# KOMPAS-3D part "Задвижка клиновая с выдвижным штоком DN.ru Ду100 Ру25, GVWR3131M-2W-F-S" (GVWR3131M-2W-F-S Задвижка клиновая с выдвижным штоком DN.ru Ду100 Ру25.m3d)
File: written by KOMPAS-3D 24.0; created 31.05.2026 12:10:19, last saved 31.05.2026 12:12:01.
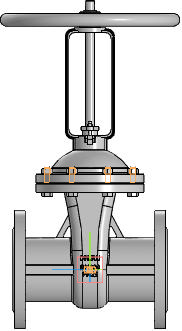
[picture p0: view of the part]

Document properties: Автор: R2D2; Полное имя файла: E:\Работа\Зайцев\GVWR3131M-2W-F-S Задвижка клиновая 30нж64нж DN.ru  Ду50-150 Ру25\исходные данные\DN100\dn100\GVWR3131M-2W-F-S Задвижка клиновая с выдвижным штоком DN.ru Ду100 Ру25.m3d

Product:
- Component [detail]: Деталь2  | qty 1  | pos. 1  | Автор: R2D2; additional columns: Типовые; source file: ..\Деталь2 Деталь2.m3d
- Component [detail]: ANSI B18.2.4.2M - M5x0,8 - 8  | designation ANSI B18.2.4.2M - M5x0,8  | qty 2  | pos. 2  | Комментарий: Типы метрических   шестигранных гаек   2; Автор: R2D2; additional columns: Сталь, мягкая; source file: ..\ANSI B18.2.4.2M - M5x0,8 ANSI B18.2.4.2M - M5x0,8 - 8.m3d
- Component [detail]: Деталь1  | qty 1  | pos. 3  | additional columns: Типовые; source file: ..\2.m3d
- Component [detail]: Деталь1  | qty 1  | pos. 3  | Автор: R2D2; additional columns: Типовые; source file: ..\3.m3d
- Component [detail]: Деталь1  | qty 2  | pos. 3  | Автор: R2D2; additional columns: Типовые; source file: ..\1.m3d
- Component [standard]: Болт М12-6gx50.88.45Г.019 ГОСТ 7798-70  | qty 8  | Материал: Сталь 45Г (density 7850 kg/m3); Масса: 0.06053; Раздел спецификации: Стандартные изделия; Рассекать на разрезах: no; additional columns: BOSimple***Material:39848d99-529e-4aa2-825c-393daa009d15
- Component [standard]: Гайка М12-6H ГОСТ 5915-70  | qty 24  | Масса: 0.0184; Раздел спецификации: Стандартные изделия; Рассекать на разрезах: no
- Part/product: Задвижка клиновая с выдвижным штоком DN.ru Ду100 Ру25  | designation GVWR3131M-2W-F-S
    Масса: 29
    Раздел спецификации: Прочие изделия
    Примечание: D040-07876

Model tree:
1. Массив по концентрической сетке:1  (labels: Грань.Твердое тело1)  (8 pattern instances)
     Шаг 2 = 360
2. Массив по концентрической сетке:2  (labels: Грань.Твердое тело1)  (2 pattern instances)
     Шаг 2 = 360
3. Элемент выдавливания:1  (with: Грань.Элемент выдавливания:2, Грань.Элемент выдавливания:1)
     Расстояние 1 = 88.75
4. Элемент выдавливания:2  (with: Грань.Элемент выдавливания:1, Грань.Элемент вращения:1)
     Расстояние 1 = 46.5338
5. Элемент выдавливания:3  (with: Грань.Элемент выдавливания:1, Грань.Элемент вращения:1)
     Расстояние 1 = 40.7931
6. Эскиз:1
7. Элемент выдавливания:4  (with: Грань.Элемент выдавливания:1, Грань.Элемент вращения:1)  (labels: Грань.Твердое тело1; Грань.Solid1; Твердое тело1)
     Расстояние 1 = 76; Смещение 1 = 1; Расстояние = -525; Расстояние = -150; Ориентация = 2

Referenced files in E:\Работа\Зайцев\GVWR3131M-2W-F-S Задвижка клиновая 30нж64нж DN.ru  Ду50-150 Ру25\исходные данные\DN100\: Деталь2 Деталь2.m3d, ANSI B18.2.4.2M - M5x0,8 ANSI B18.2.4.2M - M5x0,8 - 8.m3d, 2.m3d, 3.m3d, 1.m3d
Referenced files in C:\Program Files\ASCON\KOMPAS-3D v24\Libs\PolynomLib\DATA\vault\Methods\Kompas\3D\: PLib_Bolt_1_900.m3d, PLib_Nut_OST92_900.m3d
Referenced files in E:\Работа\Зайцев\GVWR3131M-2W-F-S Задвижка клиновая с выдвижным штоком DN.ru Ду50-200 Ру63\DN100\исходные материалы\: 1.m3d, ANSI B18.2.4.2M - M5x0,8 ANSI B18.2.4.2M - M5x0,8 - 8.m3d
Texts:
  BOSimple***PART:25ccc031-f2ed-a43b-e633-090566d53ffa***SHORTLOC:Root±30±20±10±80±10±©{}30±©{BASE}130±290[9;Цинковое, хроматированное;Сталь 45Г ГОСТ 4543-2016;50;12;19;1,75;8.8]
  BOSimple***Material:39848d99-529e-4aa2-825c-393daa009d15
  BOSimple***PART:dfaf85ed-3e43-003f-b29c-9c5b054070d3***SHORTLOC:Root±30±10±20±©{}110±10±50±60[Нет;Без покрытия;Без указания материала;-;12;1,75;19]
  GVWR3131M-2W-F-S
  DN100
  GOST 26.020 Pr3
  PN25
  Деталь2 Деталь2
  ANSI B18.2.4.2M - M5x0,8 ANSI B18.2.4.2M - M5x0,8 - 8 (1)
  Деталь1 Деталь1
  Деталь1 Деталь1 (1)
  Деталь1 Деталь1 (2)
  Болт М12-6gx50.88.45Г.019 ГОСТ 7798-70 (1)
  hole1
  hole2
  Гайка М12-6H ГОСТ 5915-70 (1)
  bcut1
  hcut1
  cut1
  Гайка М12-6H ГОСТ 5915-70 (2)
  Гайка М12-6H ГОСТ 5915-70 (3)
  Гайка М12-6H ГОСТ 5915-70 (4)
  Гайка М12-6H ГОСТ 5915-70 (5)
  Гайка М12-6H ГОСТ 5915-70 (6)
  Болт М12-6gx50.88.45Г.019 ГОСТ 7798-70 (2)
  Гайка М12-6H ГОСТ 5915-70 (7)
  Гайка М12-6H ГОСТ 5915-70 (8)
  Гайка М12-6H ГОСТ 5915-70 (9)
  Болт М12-6gx50.88.45Г.019 ГОСТ 7798-70 (3)
  Гайка М12-6H ГОСТ 5915-70 (10)
  Гайка М12-6H ГОСТ 5915-70 (11)
  Гайка М12-6H ГОСТ 5915-70 (12)
  Болт М12-6gx50.88.45Г.019 ГОСТ 7798-70 (4)
  Гайка М12-6H ГОСТ 5915-70 (13)
  Гайка М12-6H ГОСТ 5915-70 (14)
  Гайка М12-6H ГОСТ 5915-70 (15)
  Болт М12-6gx50.88.45Г.019 ГОСТ 7798-70 (5)
  Гайка М12-6H ГОСТ 5915-70 (16)
  Гайка М12-6H ГОСТ 5915-70 (17)
  Гайка М12-6H ГОСТ 5915-70 (18)
  Болт М12-6gx50.88.45Г.019 ГОСТ 7798-70 (6)
  Гайка М12-6H ГОСТ 5915-70 (19)
  Гайка М12-6H ГОСТ 5915-70 (20)
  Гайка М12-6H ГОСТ 5915-70 (21)
  Болт М12-6gx50.88.45Г.019 ГОСТ 7798-70 (7)
  Гайка М12-6H ГОСТ 5915-70 (22)
  Гайка М12-6H ГОСТ 5915-70 (23)
  Гайка М12-6H ГОСТ 5915-70 (24)
  Болт М12-6gx50.88.45Г.019 ГОСТ 7798-70 (8)
  ANSI B18.2.4.2M - M5x0,8 ANSI B18.2.4.2M - M5x0,8 - 8 (2)
  Ось Z.Начало координат
  Ось Y.Начало координат
  Плоскость ZX.Начало координат
  Плоскость XY.Начало координат
  Plane. Начало координат
  Solid1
